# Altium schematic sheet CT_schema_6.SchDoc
size 370 x 245 mm
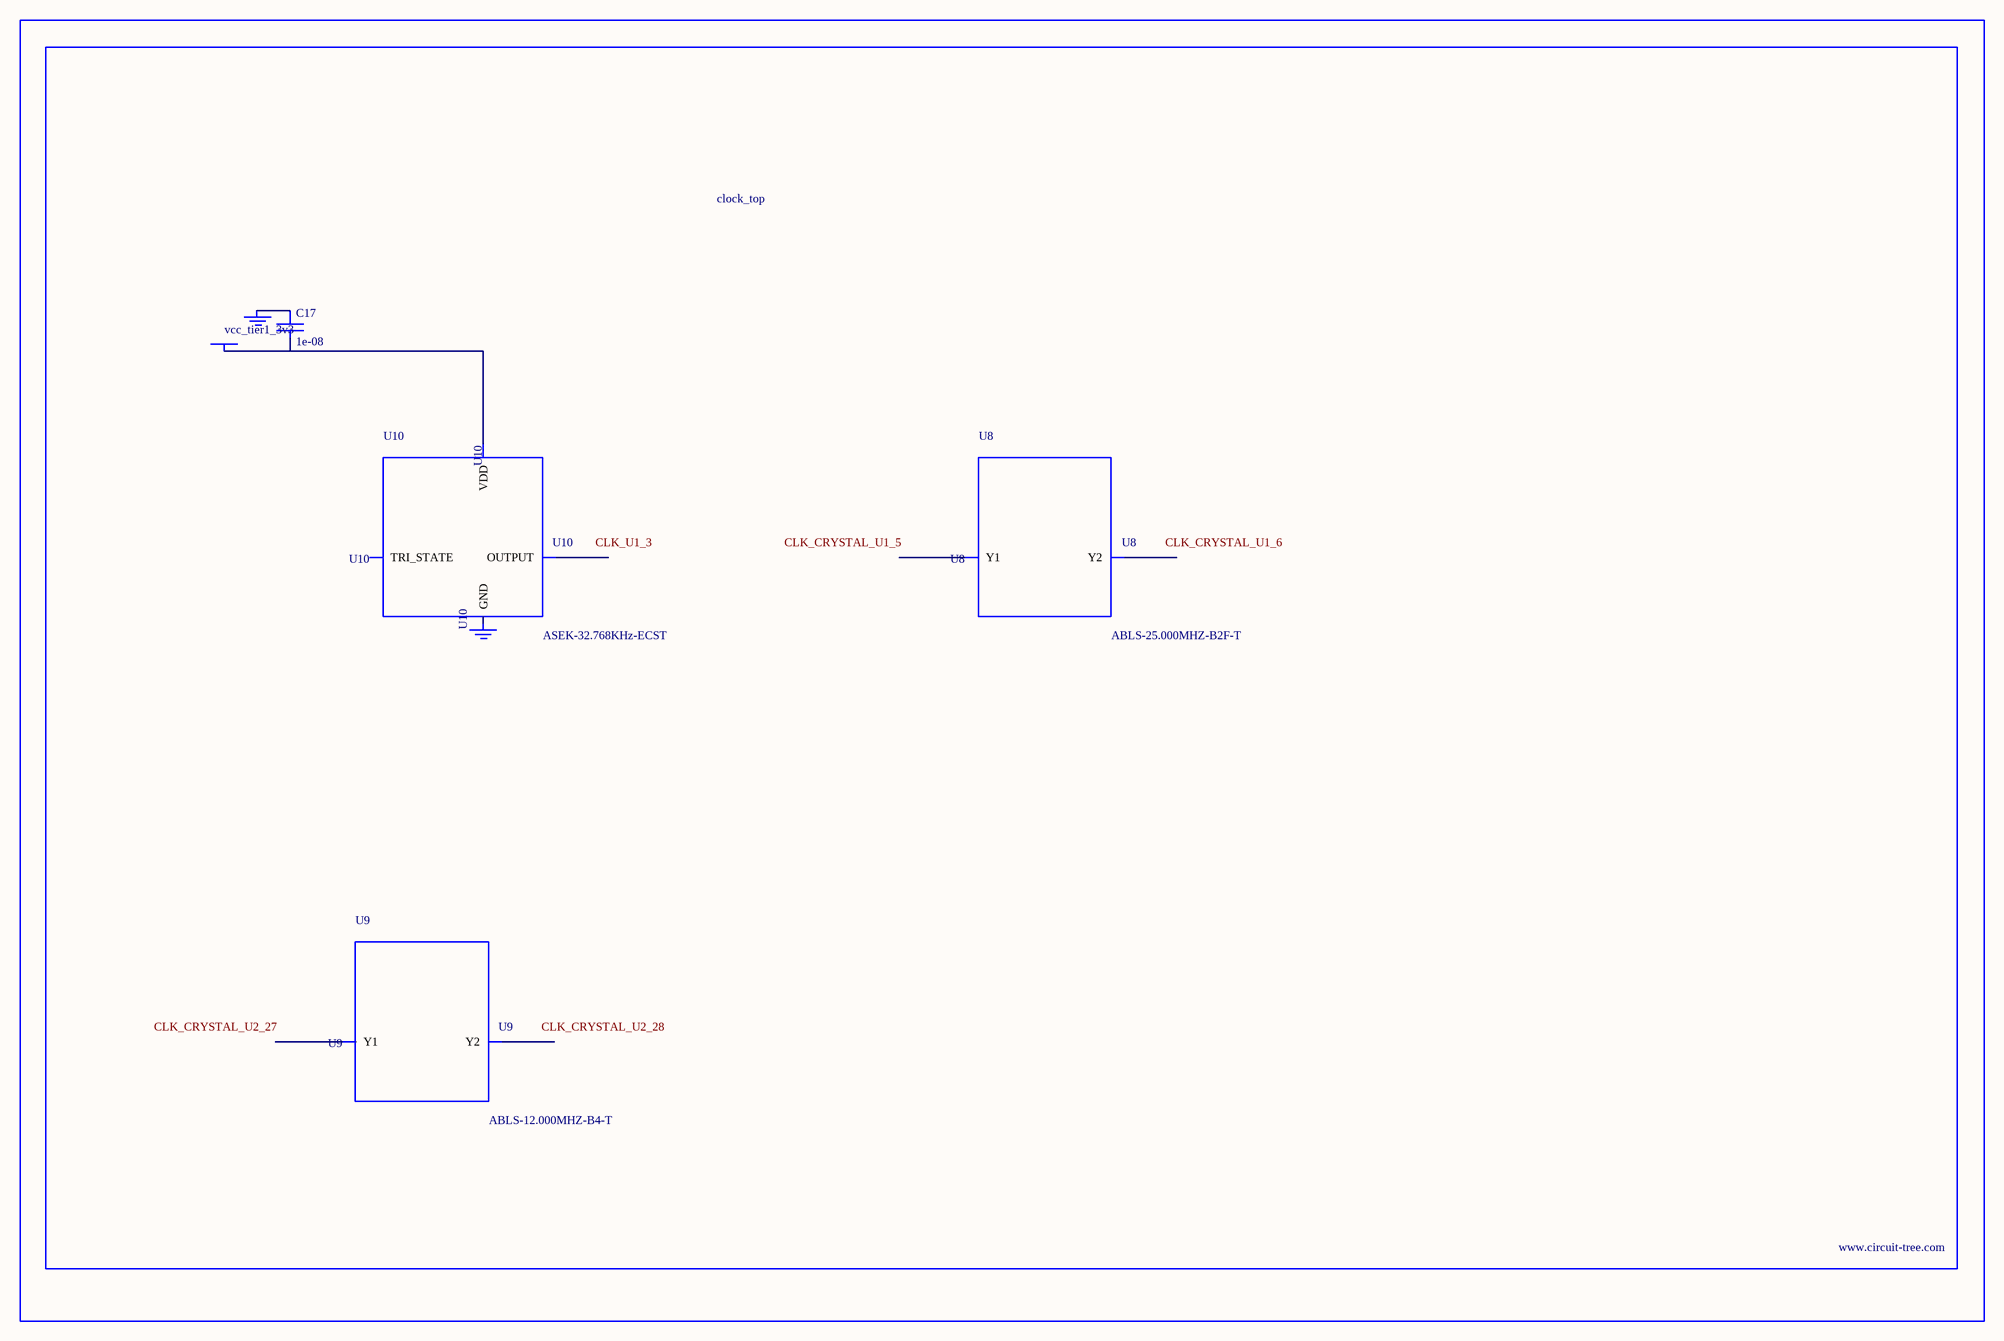
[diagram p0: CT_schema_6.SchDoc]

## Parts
BORDER5  (no value)
C17  1e-08  [C0402]
GND_INSTANCE_5_0  (no value)
GND_INSTANCE_5_1  (no value)
POWER_INSTANCE_5_0  vcc_tier1_3v3
U8  ABLS-25.000MHZ-B2F-T  [ABLS-25.000MHZ-B2F-T]
U9  ABLS-12.000MHZ-B4-T  [ABLS-12.000MHZ-B4-T]
U10  ASEK-32.768KHz-ECST  [ASEK]

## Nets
NetC17_1: C17.1 GND_INSTANCE_5_0.0(GND)
NetC17_2: C17.2 POWER_INSTANCE_5_0.0(PWR) U10.4(VDD)

Not connected (* = marked no-connect by the designer): GND_INSTANCE_5_1 0(GND); U8 1(Y1) 2(Y2); U9 1(Y1) 2(Y2); U10 1(TRI_STATE) 2(GND) 3(OUTPUT)

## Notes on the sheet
- Labels drawn without touching a wire or pin: CLK_CRYSTAL_U1_5, CLK_CRYSTAL_U1_6, CLK_CRYSTAL_U2_27, CLK_CRYSTAL_U2_28, CLK_U1_3

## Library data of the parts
BORDER5 = BORDER_PAGE5
C17 = C0402C103K3RAC
GND_INSTANCE_5_0 GND_INSTANCE_5_1 = GND
POWER_INSTANCE_5_0 = PWR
